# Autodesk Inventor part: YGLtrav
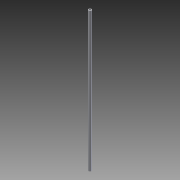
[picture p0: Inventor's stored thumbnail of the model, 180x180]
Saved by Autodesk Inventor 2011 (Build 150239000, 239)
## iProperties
Created: 2014-03
Part Number: YGLtrav
Document SubType Name: Modeling
Designer: Evgeny
Density: 1 g/cm^3
Author: Evgeny
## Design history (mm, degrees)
sketch "Эскиз1"
  geometry: C1 r 10.5 at (0, 0); C2 r 7 at (0, 0); 1 further point
  constraints: 2 centre point, 2 coincident
  dimensions: "d0" = 21 diameter of C1; "d1" = 14 diameter of C2
extrude "Выдавливание1" new body sketch "Эскиз1" distance "d2" = 810; taper "d4" = 0 deg; dims "d3" = 190, "d5" = 0
node "Твердое тело1"
